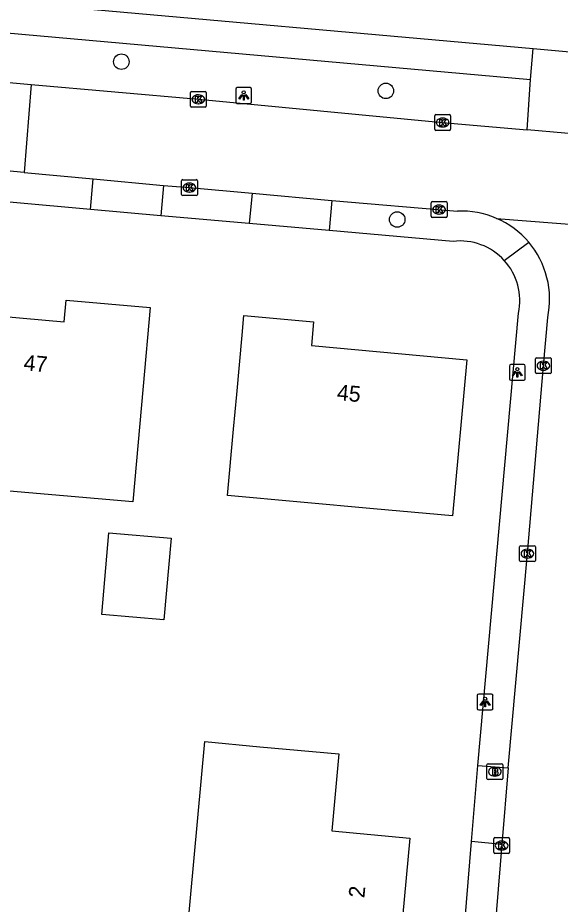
# Model space of a CAD drawing. Extents: x 162722 to 165099, y 384721 to 386283.
# Drawn here: x 163916.1 to 163950.4, y 385139 to 385195 of the extents above; entities that cross this region are included whole.
import ezdxf

# ---------------------------------------------------------------- set-up
doc = ezdxf.new("R2010")
doc.units = 0
for name, color, linetype in [('IMGEO_Boom', 7, 'Continuous'), ('IMGEO_Brandkraan', 7, 'Continuous'), ('IMGEO_Kolk', 7, 'Continuous'), ('IMGEO_Lichtpunt', 7, 'Continuous'), ('IMGEO_Pand', 7, 'Continuous'), ('IMGEO_Pand_nummerreeks', 7, 'Continuous'), ('IMGEO_Parkeervlak_open', 7, 'Continuous'), ('IMGEO_Rijbaan_lokaal_gesloten', 7, 'Continuous'), ('IMGEO_Rijbaan_lokaal_open', 7, 'Continuous'), ('IMGEO_Voetpad_open', 7, 'Continuous')]:
    doc.layers.add(name, color=color, linetype=linetype)

msp = doc.modelspace()

# ---------------------------------------------------------------- linework, layer by layer
at = {"layer": 'IMGEO_Boom'}
for centre in [(163922.656, 385192.226), (163939.353, 385190.385), (163940.069, 385182.264)]:
    msp.add_circle(centre, 0.489, dxfattribs=at)
at = {"layer": 'IMGEO_Brandkraan'}
for p, q in [((163945.732, 385146.978), (163945.732, 385147.83)), ((163945.807, 385147.904), (163946.659, 385147.904)), ((163946.733, 385147.83), (163946.733, 385146.978)), ((163946.22, 385147.684), (163946.245, 385147.684)), ((163946.659, 385146.904), (163945.807, 385146.904)), ((163946.243, 385147.124), (163946.218, 385147.124))]:
    msp.add_line(p, q, dxfattribs=at)
for points in [[(163945.732, 385146.978), (163945.732, 385147.83)], [(163945.807, 385147.904), (163946.659, 385147.904)], [(163946.733, 385147.83), (163946.733, 385146.978)], [(163946.08, 385147.604), (163946.08, 385147.204), (163946.293, 385147.204)], [(163946.311, 385147.604), (163946.08, 385147.604)], [(163946.259, 385147.523), (163946.205, 385147.523), (163946.205, 385147.447)], [(163946.205, 385147.447), (163946.258, 385147.447)], [(163946.267, 385147.371), (163946.205, 385147.371), (163946.205, 385147.29)], [(163946.205, 385147.29), (163946.267, 385147.29)], [(163946.659, 385146.904), (163945.807, 385146.904)]]:
    msp.add_lwpolyline(points, dxfattribs=at)
for centre, radius, start, end in [((163945.809, 385147.828), 0.0765, 91.552, 178.448), ((163945.809, 385147.828), 0.0765, 91.552, 178.448), ((163946.657, 385147.828), 0.0765, 1.552, 88.448), ((163946.657, 385147.828), 0.0765, 1.552, 88.448), ((163946.26, 385147.485), 0.0379, 267.8285, 90.9355), ((163946.268, 385147.33), 0.0404, 269.8759, 90.5077), ((163946.299, 385147.455), 0.251, 268.6676, 293.5347), ((163946.315, 385147.459), 0.145, 59.4692, 91.5367), ((163946.34, 385147.506), 0.0922, 285.5137, 58.1501), ((163946.345, 385147.314), 0.105, 301.3115, 78.989), ((163945.809, 385146.98), 0.0765, 181.552, 268.448), ((163945.809, 385146.98), 0.0765, 181.552, 268.448), ((163946.657, 385146.98), 0.0765, 271.552, 358.448), ((163946.657, 385146.98), 0.0765, 271.552, 358.448)]:
    msp.add_arc(centre, radius, start, end, dxfattribs=at)
for centre, major_axis, ratio, start_param, end_param in [((163946.219, 385147.404), (-0.387, 0.002), 0.722429, 4.712389, 7.853982), ((163946.244, 385147.404), (-0.39, 0.002), 0.717154, 1.570796, 4.712389)]:
    msp.add_ellipse(centre, major_axis=major_axis, ratio=ratio, start_param=start_param, end_param=end_param, dxfattribs=at)
at = {"layer": 'IMGEO_Kolk'}
for p, q in [((163927.017, 385189.429), (163927.017, 385190.281)), ((163927.092, 385190.355), (163927.944, 385190.355)), ((163928.018, 385190.281), (163928.018, 385189.429)), ((163927.505, 385190.135), (163927.53, 385190.135)), ((163927.944, 385189.355), (163927.092, 385189.355)), ((163927.528, 385189.575), (163927.503, 385189.575)), ((163942.434, 385187.962), (163942.434, 385188.814)), ((163942.509, 385188.888), (163943.361, 385188.888)), ((163942.922, 385188.668), (163942.947, 385188.668)), ((163943.435, 385188.814), (163943.435, 385187.962)), ((163942.945, 385188.108), (163942.92, 385188.108)), ((163943.361, 385187.888), (163942.509, 385187.888)), ((163926.454, 385183.854), (163926.454, 385184.706)), ((163926.529, 385184.78), (163927.381, 385184.78)), ((163927.455, 385184.706), (163927.455, 385183.854)), ((163926.942, 385184.56), (163926.967, 385184.56)), ((163927.381, 385183.78), (163926.529, 385183.78)), ((163926.965, 385184), (163926.94, 385184)), ((163942.214, 385182.466), (163942.214, 385183.318)), ((163942.289, 385183.392), (163943.141, 385183.392)), ((163942.702, 385183.172), (163942.727, 385183.172)), ((163943.215, 385183.318), (163943.215, 385182.466)), ((163942.725, 385182.612), (163942.7, 385182.612)), ((163943.141, 385182.392), (163942.289, 385182.392)), ((163948.872, 385173.533), (163949.724, 385173.533)), ((163948.797, 385172.607), (163948.797, 385173.459)), ((163949.285, 385173.313), (163949.31, 385173.313)), ((163949.798, 385173.459), (163949.798, 385172.607)), ((163949.724, 385172.533), (163948.872, 385172.533)), ((163949.308, 385172.753), (163949.283, 385172.753)), ((163947.79, 385160.745), (163947.79, 385161.597)), ((163947.865, 385161.671), (163948.717, 385161.671)), ((163948.278, 385161.451), (163948.303, 385161.451)), ((163948.791, 385161.597), (163948.791, 385160.745)), ((163948.717, 385160.671), (163947.865, 385160.671)), ((163948.301, 385160.891), (163948.276, 385160.891)), ((163946.238, 385143.243), (163947.09, 385143.243)), ((163946.163, 385142.317), (163946.163, 385143.169)), ((163946.651, 385143.023), (163946.676, 385143.023)), ((163947.164, 385143.169), (163947.164, 385142.317)), ((163947.09, 385142.243), (163946.238, 385142.243)), ((163946.674, 385142.463), (163946.649, 385142.463))]:
    msp.add_line(p, q, dxfattribs=at)
for points in [[(163927.017, 385189.429), (163927.017, 385190.281)], [(163927.092, 385190.355), (163927.944, 385190.355)], [(163928.018, 385190.281), (163928.018, 385189.429)], [(163927.338, 385190.055), (163927.461, 385190.055), (163927.461, 385189.904), (163927.591, 385190.055), (163927.755, 385190.055), (163927.609, 385189.904), (163927.762, 385189.655), (163927.61, 385189.655), (163927.525, 385189.819), (163927.461, 385189.752), (163927.461, 385189.655), (163927.338, 385189.655), (163927.338, 385190.055)], [(163927.944, 385189.355), (163927.092, 385189.355)], [(163942.434, 385187.962), (163942.434, 385188.814)], [(163942.509, 385188.888), (163943.361, 385188.888)], [(163942.755, 385188.588), (163942.878, 385188.588), (163942.878, 385188.437), (163943.008, 385188.588), (163943.172, 385188.588), (163943.026, 385188.437), (163943.179, 385188.188), (163943.027, 385188.188), (163942.942, 385188.352), (163942.878, 385188.285), (163942.878, 385188.188), (163942.755, 385188.188), (163942.755, 385188.588)], [(163943.435, 385188.814), (163943.435, 385187.962)], [(163943.361, 385187.888), (163942.509, 385187.888)], [(163926.454, 385183.854), (163926.454, 385184.706)], [(163926.529, 385184.78), (163927.381, 385184.78)], [(163927.455, 385184.706), (163927.455, 385183.854)], [(163926.775, 385184.48), (163926.898, 385184.48), (163926.898, 385184.329), (163927.028, 385184.48), (163927.192, 385184.48), (163927.046, 385184.329), (163927.199, 385184.08), (163927.047, 385184.08), (163926.962, 385184.244), (163926.898, 385184.177), (163926.898, 385184.08), (163926.775, 385184.08), (163926.775, 385184.48)], [(163927.381, 385183.78), (163926.529, 385183.78)], [(163942.214, 385182.466), (163942.214, 385183.318)], [(163942.289, 385183.392), (163943.141, 385183.392)], [(163942.535, 385183.092), (163942.658, 385183.092), (163942.658, 385182.941), (163942.788, 385183.092), (163942.952, 385183.092), (163942.806, 385182.941), (163942.959, 385182.692), (163942.807, 385182.692), (163942.722, 385182.856), (163942.658, 385182.789), (163942.658, 385182.692), (163942.535, 385182.692), (163942.535, 385183.092)], [(163943.215, 385183.318), (163943.215, 385182.466)], [(163943.141, 385182.392), (163942.289, 385182.392)], [(163948.872, 385173.533), (163949.724, 385173.533)], [(163948.797, 385172.607), (163948.797, 385173.459)], [(163949.118, 385173.233), (163949.241, 385173.233), (163949.241, 385173.082), (163949.371, 385173.233), (163949.535, 385173.233), (163949.389, 385173.082), (163949.542, 385172.833), (163949.39, 385172.833), (163949.305, 385172.997), (163949.241, 385172.93), (163949.241, 385172.833), (163949.118, 385172.833), (163949.118, 385173.233)], [(163949.798, 385173.459), (163949.798, 385172.607)], [(163949.724, 385172.533), (163948.872, 385172.533)], [(163947.79, 385160.745), (163947.79, 385161.597)], [(163947.865, 385161.671), (163948.717, 385161.671)], [(163948.111, 385161.371), (163948.234, 385161.371), (163948.234, 385161.22), (163948.364, 385161.371), (163948.528, 385161.371), (163948.382, 385161.22), (163948.535, 385160.971), (163948.383, 385160.971), (163948.298, 385161.135), (163948.234, 385161.068), (163948.234, 385160.971), (163948.111, 385160.971), (163948.111, 385161.371)], [(163948.791, 385161.597), (163948.791, 385160.745)], [(163948.717, 385160.671), (163947.865, 385160.671)], [(163946.238, 385143.243), (163947.09, 385143.243)], [(163946.163, 385142.317), (163946.163, 385143.169)], [(163946.484, 385142.943), (163946.607, 385142.943), (163946.607, 385142.792), (163946.737, 385142.943), (163946.901, 385142.943), (163946.755, 385142.792), (163946.908, 385142.543), (163946.756, 385142.543), (163946.671, 385142.707), (163946.607, 385142.64), (163946.607, 385142.543), (163946.484, 385142.543), (163946.484, 385142.943)], [(163947.164, 385143.169), (163947.164, 385142.317)], [(163947.09, 385142.243), (163946.238, 385142.243)]]:
    msp.add_lwpolyline(points, dxfattribs=at)
for centre, start, end in [((163927.094, 385190.279), 91.552, 178.448), ((163927.094, 385190.279), 91.552, 178.448), ((163927.942, 385190.279), 1.552, 88.448), ((163927.942, 385190.279), 1.552, 88.448), ((163927.094, 385189.431), 181.552, 268.448), ((163927.094, 385189.431), 181.552, 268.448), ((163927.942, 385189.431), 271.552, 358.448), ((163927.942, 385189.431), 271.552, 358.448), ((163942.511, 385188.812), 91.552, 178.448), ((163942.511, 385188.812), 91.552, 178.448), ((163943.359, 385188.812), 1.552, 88.448), ((163943.359, 385188.812), 1.552, 88.448), ((163942.511, 385187.964), 181.552, 268.448), ((163942.511, 385187.964), 181.552, 268.448), ((163943.359, 385187.964), 271.552, 358.448), ((163943.359, 385187.964), 271.552, 358.448), ((163926.531, 385184.704), 91.552, 178.448), ((163926.531, 385184.704), 91.552, 178.448), ((163927.379, 385184.704), 1.552, 88.448), ((163927.379, 385184.704), 1.552, 88.448), ((163926.531, 385183.856), 181.552, 268.448), ((163926.531, 385183.856), 181.552, 268.448), ((163927.379, 385183.856), 271.552, 358.448), ((163927.379, 385183.856), 271.552, 358.448), ((163942.291, 385183.316), 91.552, 178.448), ((163942.291, 385183.316), 91.552, 178.448), ((163943.139, 385183.316), 1.552, 88.448), ((163943.139, 385183.316), 1.552, 88.448), ((163942.291, 385182.468), 181.552, 268.448), ((163942.291, 385182.468), 181.552, 268.448), ((163943.139, 385182.468), 271.552, 358.448), ((163943.139, 385182.468), 271.552, 358.448), ((163948.874, 385173.457), 91.552, 178.448), ((163948.874, 385173.457), 91.552, 178.448), ((163949.722, 385173.457), 1.552, 88.448), ((163949.722, 385173.457), 1.552, 88.448), ((163948.874, 385172.609), 181.552, 268.448), ((163948.874, 385172.609), 181.552, 268.448), ((163949.722, 385172.609), 271.552, 358.448), ((163949.722, 385172.609), 271.552, 358.448), ((163947.867, 385161.595), 91.552, 178.448), ((163947.867, 385161.595), 91.552, 178.448), ((163948.715, 385161.595), 1.552, 88.448), ((163948.715, 385161.595), 1.552, 88.448), ((163947.867, 385160.747), 181.552, 268.448), ((163947.867, 385160.747), 181.552, 268.448), ((163948.715, 385160.747), 271.552, 358.448), ((163948.715, 385160.747), 271.552, 358.448), ((163946.24, 385143.167), 91.552, 178.448), ((163946.24, 385143.167), 91.552, 178.448), ((163947.088, 385143.167), 1.552, 88.448), ((163947.088, 385143.167), 1.552, 88.448), ((163946.24, 385142.319), 181.552, 268.448), ((163946.24, 385142.319), 181.552, 268.448), ((163947.088, 385142.319), 271.552, 358.448), ((163947.088, 385142.319), 271.552, 358.448)]:
    msp.add_arc(centre, 0.0765, start, end, dxfattribs=at)
for centre, major_axis, ratio, start_param, end_param in [((163927.504, 385189.855), (-0.387, 0.002), 0.722429, 4.712389, 7.853982), ((163927.529, 385189.855), (-0.39, 0.002), 0.717154, 1.570796, 4.712389), ((163942.921, 385188.388), (-0.387, 0.002), 0.722429, 4.712389, 7.853982), ((163942.946, 385188.388), (-0.39, 0.002), 0.717154, 1.570796, 4.712389), ((163926.941, 385184.28), (-0.387, 0.002), 0.722429, 4.712389, 7.853982), ((163926.966, 385184.28), (-0.39, 0.002), 0.717154, 1.570796, 4.712389), ((163942.701, 385182.892), (-0.387, 0.002), 0.722429, 4.712389, 7.853982), ((163942.726, 385182.892), (-0.39, 0.002), 0.717154, 1.570796, 4.712389), ((163949.284, 385173.033), (-0.387, 0.002), 0.722429, 4.712389, 7.853982), ((163949.309, 385173.033), (-0.39, 0.002), 0.717154, 1.570796, 4.712389), ((163948.277, 385161.171), (-0.387, 0.002), 0.722429, 4.712389, 7.853982), ((163948.302, 385161.171), (-0.39, 0.002), 0.717154, 1.570796, 4.712389), ((163946.65, 385142.743), (-0.387, 0.002), 0.722429, 4.712389, 7.853982), ((163946.675, 385142.743), (-0.39, 0.002), 0.717154, 1.570796, 4.712389)]:
    msp.add_ellipse(centre, major_axis=major_axis, ratio=ratio, start_param=start_param, end_param=end_param, dxfattribs=at)
at = {"layer": 'IMGEO_Lichtpunt'}
for p, q in [((163929.882, 385190.495), (163929.882, 385189.688)), ((163929.882, 385190.495), (163929.882, 385189.688)), ((163930.784, 385190.59), (163929.976, 385190.59)), ((163930.784, 385190.59), (163929.976, 385190.59)), ((163930.878, 385189.688), (163930.878, 385190.495)), ((163930.878, 385189.688), (163930.878, 385190.495)), ((163929.976, 385189.594), (163930.784, 385189.594)), ((163929.976, 385189.594), (163930.784, 385189.594)), ((163947.151, 385173.016), (163947.151, 385172.209)), ((163947.151, 385173.016), (163947.151, 385172.209)), ((163948.053, 385173.111), (163947.245, 385173.111)), ((163948.053, 385173.111), (163947.245, 385173.111)), ((163948.147, 385172.209), (163948.147, 385173.016)), ((163948.147, 385172.209), (163948.147, 385173.016)), ((163947.245, 385172.115), (163948.053, 385172.115)), ((163947.245, 385172.115), (163948.053, 385172.115)), ((163945.12, 385152.21), (163945.12, 385151.403)), ((163945.12, 385152.21), (163945.12, 385151.403)), ((163946.022, 385152.305), (163945.214, 385152.305)), ((163946.022, 385152.305), (163945.214, 385152.305)), ((163946.116, 385151.403), (163946.116, 385152.21)), ((163946.116, 385151.403), (163946.116, 385152.21)), ((163945.214, 385151.309), (163946.022, 385151.309)), ((163945.214, 385151.309), (163946.022, 385151.309))]:
    msp.add_line(p, q, dxfattribs=at)
for points in [[(163930.256, 385190.159), (163930.295, 385190.131), (163930.107, 385189.869), (163930.069, 385189.896), (163930.256, 385190.159)], [(163930.358, 385190.111), (163930.405, 385190.111), (163930.405, 385189.789), (163930.358, 385189.789), (163930.358, 385190.111)], [(163930.468, 385190.131), (163930.506, 385190.158), (163930.693, 385189.896), (163930.654, 385189.868), (163930.468, 385190.131)], [(163947.525, 385172.68), (163947.564, 385172.652), (163947.376, 385172.39), (163947.338, 385172.417), (163947.525, 385172.68)], [(163947.627, 385172.632), (163947.674, 385172.632), (163947.674, 385172.31), (163947.627, 385172.31), (163947.627, 385172.632)], [(163947.737, 385172.652), (163947.775, 385172.679), (163947.962, 385172.417), (163947.923, 385172.389), (163947.737, 385172.652)], [(163945.494, 385151.874), (163945.533, 385151.846), (163945.345, 385151.584), (163945.307, 385151.611), (163945.494, 385151.874)], [(163945.596, 385151.826), (163945.643, 385151.826), (163945.643, 385151.504), (163945.596, 385151.504), (163945.596, 385151.826)], [(163945.706, 385151.846), (163945.744, 385151.873), (163945.931, 385151.611), (163945.892, 385151.583), (163945.706, 385151.846)]]:
    msp.add_lwpolyline(points, dxfattribs=at)
for centre in [(163930.381, 385190.293), (163947.65, 385172.814), (163945.619, 385152.008)]:
    msp.add_circle(centre, 0.0994, dxfattribs=at)
for centre, start, end in [((163929.976, 385190.495), 90, 180), ((163929.976, 385190.495), 90, 180), ((163930.784, 385190.495), 0, 90), ((163930.784, 385190.495), 0, 90), ((163929.976, 385189.688), 180, 270), ((163929.976, 385189.688), 180, 270), ((163930.784, 385189.688), 270, 0), ((163930.784, 385189.688), 270, 360), ((163947.245, 385173.016), 90, 180), ((163947.245, 385173.016), 90, 180), ((163948.053, 385173.016), 0, 90), ((163948.053, 385173.016), 0, 90), ((163947.245, 385172.209), 180, 270), ((163947.245, 385172.209), 180, 270), ((163948.053, 385172.209), 270, 0), ((163948.053, 385172.209), 270, 360), ((163945.214, 385152.21), 90, 180), ((163945.214, 385152.21), 90, 180), ((163946.022, 385152.21), 0, 90), ((163946.022, 385152.21), 0, 90), ((163945.214, 385151.403), 180, 270), ((163945.214, 385151.403), 180, 270), ((163946.022, 385151.403), 270, 0), ((163946.022, 385151.403), 270, 360)]:
    msp.add_arc(centre, 0.0946, start, end, dxfattribs=at)
at = {"layer": 'IMGEO_Pand'}
for points in [[(163909.931, 385166.677), (163910.359, 385171.554), (163910.796, 385176.534), (163919.046, 385175.81), (163919.167, 385177.18), (163924.469, 385176.715), (163924.032, 385171.735), (163923.391, 385164.434), (163914.604, 385165.205), (163914.696, 385166.259), (163909.931, 385166.677)], [(163930.28, 385174.959), (163930.393, 385176.203), (163934.794, 385175.802), (163934.658, 385174.304), (163944.459, 385173.413), (163943.562, 385163.549), (163938.583, 385164.002), (163929.36, 385164.84), (163929.742, 385169.039), (163929.94, 385171.224), (163930.28, 385174.959)], [(163921.424, 385157.334), (163921.876, 385162.483), (163925.8, 385162.138), (163925.348, 385156.99), (163921.424, 385157.334)], [(163926.79, 385136.924), (163927.93, 385149.301), (163931.403, 385148.981), (163936.381, 385148.522), (163935.933, 385143.661), (163940.873, 385143.206), (163940.181, 385135.69)]]:
    msp.add_lwpolyline(points, dxfattribs=at)
at = {"layer": 'IMGEO_Parkeervlak_open'}
for points in [[(163920.708, 385182.9), (163891.867, 385185.503)], [(163930.724, 385182.023), (163925.145, 385182.505)], [(163943.594, 385180.886), (163935.769, 385181.571)], [(163946.824, 385179.682), (163948.37, 385180.834)], [(163945.158, 385147.789), (163947.718, 385176.353)]]:
    msp.add_lwpolyline(points, dxfattribs=at)
for centre, start, end in [((163944.042, 385177.153), 42.2729, 96.8406), ((163944.044, 385177.151), 347.7465, 42.3177)]:
    msp.add_arc(centre, 3.76, start, end, dxfattribs=at)
at = {"layer": 'IMGEO_Rijbaan_lokaal_gesloten'}
for points in [[(163916.96, 385190.797), (163916.522, 385185.239)], [(163916.96, 385190.797), (163927.518, 385189.855), (163942.935, 385188.388), (163948.264, 385187.936)], [(163953.03, 385187.504), (163948.264, 385187.936)], [(163916.522, 385185.239), (163920.884, 385184.835)], [(163920.884, 385184.835), (163925.324, 385184.422)], [(163925.324, 385184.422), (163926.955, 385184.28), (163930.915, 385183.92)], [(163930.915, 385183.92), (163935.948, 385183.471)], [(163935.948, 385183.471), (163943.865, 385182.791)], [(163946.345, 385182.337), (163959.871, 385181.283)], [(163947.078, 385147.645), (163948.291, 385161.171), (163949.298, 385173.033), (163949.567, 385176.071)], [(163947.078, 385147.645), (163946.667, 385142.814)], [(163946.667, 385142.814), (163945.777, 385131.775), (163945.709, 385130.132), (163945.758, 385129.198), (163945.828, 385128.235)]]:
    msp.add_lwpolyline(points, dxfattribs=at)
for centre, radius, start, end in [((163944.127, 385177.221), 5.576, 66.5603, 92.6918), ((163944.136, 385177.245), 5.551, 40.2873, 66.5454), ((163944.132, 385177.237), 5.559, 347.8914, 40.3226)]:
    msp.add_arc(centre, radius, start, end, dxfattribs=at)
at = {"layer": 'IMGEO_Rijbaan_lokaal_open'}
for points in [[(163914.179, 385191.045), (163916.96, 385190.797)], [(163916.522, 385185.239), (163909.369, 385185.902), (163894.427, 385187.21), (163891.915, 385187.424)]]:
    msp.add_lwpolyline(points, dxfattribs=at)
at = {"layer": 'IMGEO_Voetpad_open'}
for points in [[(163917.358, 385195.848), (163948.65, 385193.052)], [(163914.219, 385194.159), (163948.493, 385191.096)], [(163948.493, 385191.096), (163948.65, 385193.052)], [(163948.65, 385193.052), (163953.489, 385192.612)], [(163948.264, 385187.936), (163948.493, 385191.096)], [(163920.708, 385182.9), (163920.884, 385184.835)], [(163925.324, 385184.422), (163925.145, 385182.505)], [(163930.915, 385183.92), (163930.724, 385182.023)], [(163935.948, 385183.471), (163935.769, 385181.571)], [(163925.145, 385182.505), (163920.708, 385182.9)], [(163935.769, 385181.571), (163930.724, 385182.023)], [(163944.749, 385142.995), (163945.158, 385147.789)], [(163945.158, 385147.789), (163947.078, 385147.645)], [(163943.805, 385131.438), (163944.749, 385142.995)], [(163946.667, 385142.814), (163944.749, 385142.995)]]:
    msp.add_lwpolyline(points, dxfattribs=at)

# ---------------------------------------------------------------- texts
at = {"layer": 'IMGEO_Pand_nummerreeks'}
for s, rotation, p in [('47', 354.9847, (163916.463, 385172.743)), ('45', 354.8056, (163936.238, 385170.866)), ('2', 84.7362, (163937.992, 385139.403))]:
    msp.add_text(s, height=1, rotation=rotation, dxfattribs=at).set_placement(p)

doc.saveas('drawing.dxf')
